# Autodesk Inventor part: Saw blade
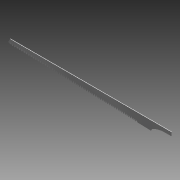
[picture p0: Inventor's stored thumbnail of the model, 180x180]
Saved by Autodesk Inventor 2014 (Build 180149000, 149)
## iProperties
Created: 2008-06
Part Number: Saw blade
Document SubType Name: Modeling
Designer: tangg
Density: 7.85 g/cm^3
Mass: 1.14139 g
Surface Area: 40.1035 cm^2
Volume: 1.14139 cm^3
Material: Alloy Steel
Appearance: Chrome - Polished
Author: tangg
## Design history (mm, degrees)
sketch "Sketch1"
  geometry: L1 (0, 6.35)-(-203.2, 6.35); L2 (-203.2, 6.35)-(-205.95, 1.588); L3 (-203.2, 0)-(-11.113, -5.983); L4 (-205.95, 1.588)-(-203.2, 0); L5 (0, 6.35)-(16.768, 6.35); L6 (16.768, 1.439)-(16.768, 6.35); L7 (16.768, 1.439)-(7.938, 1.328); L8 (-9.525, -3.175)-(-11.113, -5.983); A1 r 34.284 centre (7.465, -32.953) between (7.938, 1.328) and (-9.525, -3.175); 1 further point
  constraints: 16 end point, 2 point on circle, 1 centre point
  dimensions: "d2" = 120 deg angle of L1 L2; "d3" = 203.2 distance of L1.start L1.end; "d6" = 6.35 distance from line of L1 L3.start
extrude "Extrusion3" new body sketch "Sketch1" stored distance "d15" = 0.635; taper "d16" = 0 deg
sketch "Sketch2"
  geometry: L1 (-31.869, -5.337)-(-31.816, -2.797); L2 (-31.816, -2.797)-(-29.304, -5.416); L3 (-11.113, -5.983)-(-203.2, 0) reference; 1 further point
  constraints: 4 end point, 2 point on line
  dimensions: "d7" = 31.75 distance from line of point (0, 0) L1; "d8" = 2.54 vertical distance of L1.start L1.end; "d9" = 45 deg angle of L2 L1
extrude "Extrusion4" cut sketch "Sketch2" stored distance "d17" = 3.175; taper "d18" = 0 deg
body "Solid1"
pattern_linear "Rectangular Pattern1" dims "d14" = 3.175
